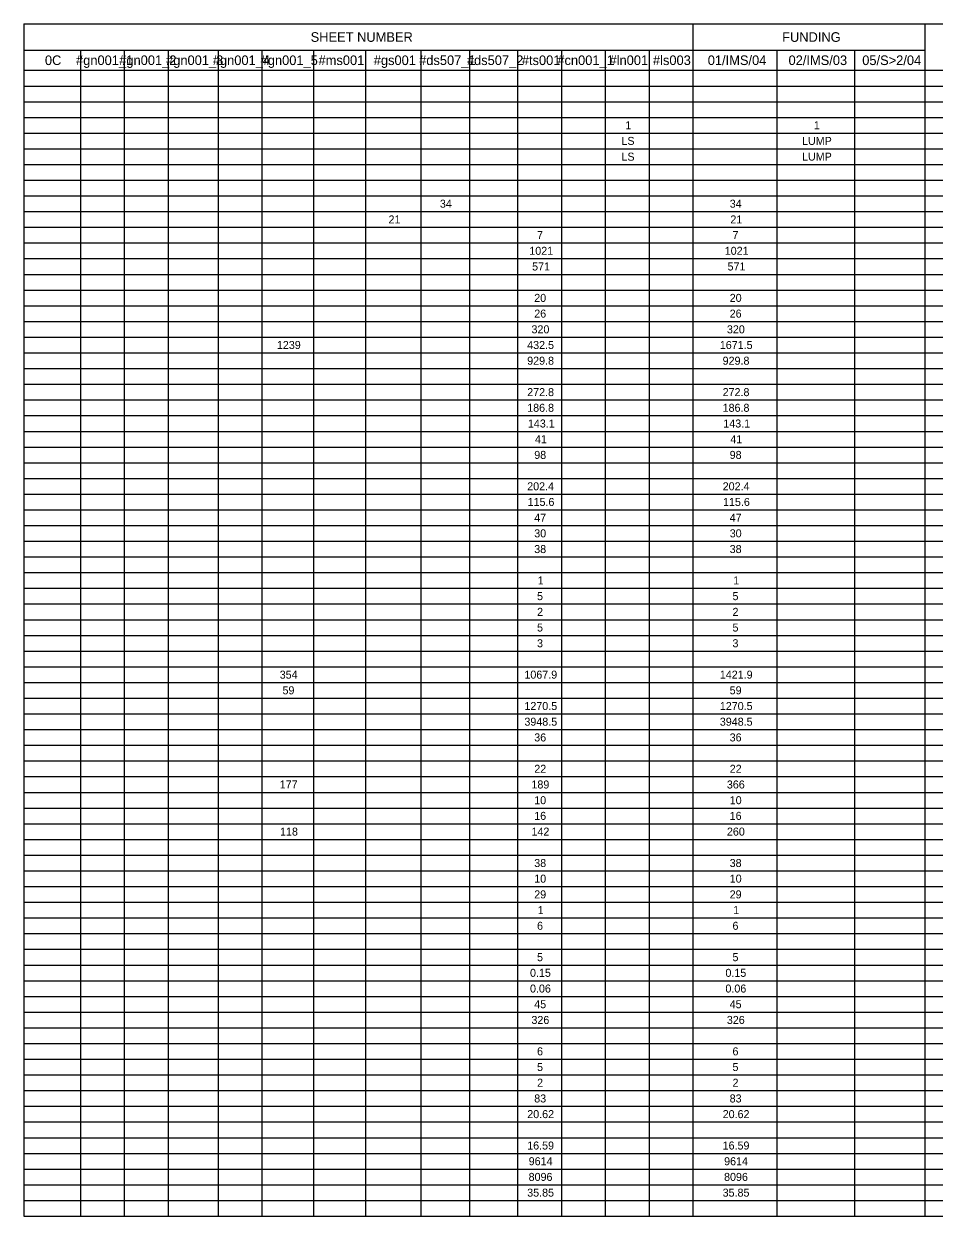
# Model space of a CAD drawing. Extents: x -542 to 295, y -281 to 32.
# Drawn here: x -541.77 to -525.86, y -100.44 to -79.59 of the extents above; entities that cross this region are included whole.
import ezdxf

# ---------------------------------------------------------------- set-up
doc = ezdxf.new("R2010")
doc.units = 0
doc.layers.add('SH_Data', color=7, linetype='Continuous')
doc.layers.add('SH_Text', color=7, linetype='Continuous')

msp = doc.modelspace()

# ---------------------------------------------------------------- linework, layer by layer
at = {"layer": 'SH_Data'}
for p, q in [((-541.766, -79.593), (-511.266, -79.593)), ((-541.766, -79.593), (-541.766, -100.444)), ((-530.071, -79.593), (-530.071, -100.444)), ((-526.016, -79.593), (-526.016, -100.444)), ((-541.766, -80.054), (-526.016, -80.054)), ((-540.776, -80.054), (-540.776, -100.444)), ((-540.01, -80.054), (-540.01, -100.444)), ((-539.244, -80.054), (-539.244, -100.444)), ((-538.371, -80.054), (-538.371, -100.444)), ((-537.605, -80.054), (-537.605, -100.444)), ((-536.701, -80.054), (-536.701, -100.444)), ((-535.796, -80.054), (-535.796, -100.444)), ((-534.828, -80.054), (-534.828, -100.444)), ((-533.976, -80.054), (-533.976, -100.444)), ((-533.135, -80.054), (-533.135, -100.444)), ((-532.369, -80.054), (-532.369, -100.444)), ((-531.603, -80.054), (-531.603, -100.444)), ((-530.837, -80.054), (-530.837, -100.444)), ((-528.602, -80.054), (-528.602, -100.444)), ((-527.25, -80.054), (-527.25, -100.444)), ((-541.766, -80.405), (-511.266, -80.405)), ((-541.766, -80.68), (-511.266, -80.68)), ((-541.766, -80.954), (-511.266, -80.954)), ((-541.766, -81.229), (-511.266, -81.229)), ((-541.766, -81.503), (-511.266, -81.503)), ((-541.766, -81.778), (-511.266, -81.778)), ((-541.766, -82.052), (-511.266, -82.052)), ((-541.766, -82.327), (-511.266, -82.327)), ((-541.766, -82.601), (-511.266, -82.601)), ((-541.766, -82.876), (-511.266, -82.876)), ((-541.766, -83.15), (-511.266, -83.15)), ((-541.766, -83.425), (-511.266, -83.425)), ((-541.766, -83.699), (-511.266, -83.699)), ((-541.766, -83.974), (-511.266, -83.974)), ((-541.766, -84.248), (-511.266, -84.248)), ((-541.766, -84.523), (-511.266, -84.523)), ((-541.766, -84.797), (-511.266, -84.797)), ((-541.766, -85.072), (-511.266, -85.072)), ((-541.766, -85.346), (-511.266, -85.346)), ((-541.766, -85.621), (-511.266, -85.621)), ((-541.766, -85.895), (-511.266, -85.895)), ((-541.766, -86.17), (-511.266, -86.17)), ((-541.766, -86.444), (-511.266, -86.444)), ((-541.766, -86.719), (-511.266, -86.719)), ((-541.766, -86.993), (-511.266, -86.993)), ((-541.766, -87.268), (-511.266, -87.268)), ((-541.766, -87.542), (-511.266, -87.542)), ((-541.766, -87.817), (-511.266, -87.817)), ((-541.766, -88.091), (-511.266, -88.091)), ((-541.766, -88.366), (-511.266, -88.366)), ((-541.766, -88.64), (-511.266, -88.64)), ((-541.766, -88.915), (-511.266, -88.915)), ((-541.766, -89.189), (-511.266, -89.189)), ((-541.766, -89.464), (-511.266, -89.464)), ((-541.766, -89.738), (-511.266, -89.738)), ((-541.766, -90.013), (-511.266, -90.013)), ((-541.766, -90.287), (-511.266, -90.287)), ((-541.766, -90.562), (-511.266, -90.562)), ((-541.766, -90.836), (-511.266, -90.836)), ((-541.766, -91.111), (-511.266, -91.111)), ((-541.766, -91.385), (-511.266, -91.385)), ((-541.766, -91.66), (-511.266, -91.66)), ((-541.766, -91.935), (-511.266, -91.935)), ((-541.766, -92.209), (-511.266, -92.209)), ((-541.766, -92.484), (-511.266, -92.484)), ((-541.766, -92.758), (-511.266, -92.758)), ((-541.766, -93.033), (-511.266, -93.033)), ((-541.766, -93.307), (-511.266, -93.307)), ((-541.766, -93.582), (-511.266, -93.582)), ((-541.766, -93.856), (-511.266, -93.856)), ((-541.766, -94.131), (-511.266, -94.131)), ((-541.766, -94.405), (-511.266, -94.405)), ((-541.766, -94.68), (-511.266, -94.68)), ((-541.766, -94.954), (-511.266, -94.954)), ((-541.766, -95.229), (-511.266, -95.229)), ((-541.766, -95.503), (-511.266, -95.503)), ((-541.766, -95.778), (-511.266, -95.778)), ((-541.766, -96.052), (-511.266, -96.052)), ((-541.766, -96.327), (-511.266, -96.327)), ((-541.766, -96.601), (-511.266, -96.601)), ((-541.766, -96.876), (-511.266, -96.876)), ((-541.766, -97.15), (-511.266, -97.15)), ((-541.766, -97.425), (-511.266, -97.425)), ((-541.766, -97.699), (-511.266, -97.699)), ((-541.766, -97.974), (-511.266, -97.974)), ((-541.766, -98.248), (-511.266, -98.248)), ((-541.766, -98.523), (-511.266, -98.523)), ((-541.766, -98.797), (-511.266, -98.797)), ((-541.766, -99.072), (-511.266, -99.072)), ((-541.766, -99.346), (-511.266, -99.346)), ((-541.766, -99.621), (-511.266, -99.621)), ((-541.766, -99.895), (-511.266, -99.895)), ((-541.766, -100.17), (-511.266, -100.17)), ((-541.766, -100.444), (-511.266, -100.444))]:
    msp.add_line(p, q, dxfattribs=at)

# ---------------------------------------------------------------- texts
at = {"layer": 'SH_Text'}
for s, height, p in [('SHEET NUMBER', 0.168, (-536.753, -79.907)), ('FUNDING', 0.168, (-528.512, -79.907)), ('0C', 0.168, (-541.398, -80.313)), ('#gn001_1', 0.168, (-540.854, -80.313)), ('#gn001_2', 0.168, (-540.099, -80.313)), ('#gn001_3', 0.168, (-539.28, -80.313)), ('#gn001_4', 0.168, (-538.463, -80.313)), ('#gn001_5', 0.168, (-537.627, -80.313)), ('#ms001', 0.168, (-536.615, -80.313)), ('#gs001', 0.168, (-535.65, -80.313)), ('#ds507_1', 0.168, (-534.857, -80.313)), ('#ds507_2', 0.168, (-534.022, -80.313)), ('#ts001', 0.168, (-533.062, -80.313)), ('#cn001_1', 0.168, (-532.441, -80.313)), ('#ln001', 0.168, (-531.529, -80.313)), ('#ls003', 0.168, (-530.77, -80.313)), ('01/IMS/04', 0.168, (-529.812, -80.313)), ('02/IMS/03', 0.168, (-528.4, -80.313)), ('05/S>2/04', 0.168, (-527.112, -80.313)), ('1', 0.14, (-531.252, -81.436)), ('1', 0.14, (-527.958, -81.436)), ('LS', 0.14, (-531.321, -81.71)), ('LUMP', 0.14, (-528.164, -81.71)), ('LS', 0.14, (-531.321, -81.985)), ('LUMP', 0.14, (-528.164, -81.985)), ('34', 0.14, (-534.494, -82.808)), ('34', 0.14, (-529.428, -82.808)), ('21', 0.14, (-535.392, -83.083)), ('21', 0.14, (-529.417, -83.083)), ('7', 0.14, (-532.796, -83.357)), ('7', 0.14, (-529.38, -83.357)), ('1021', 0.14, (-532.931, -83.632)), ('1021', 0.14, (-529.515, -83.632)), ('571', 0.14, (-532.882, -83.906)), ('571', 0.14, (-529.466, -83.906)), ('20', 0.14, (-532.845, -84.455)), ('20', 0.14, (-529.428, -84.455)), ('26', 0.14, (-532.845, -84.73)), ('26', 0.14, (-529.429, -84.73)), ('320', 0.14, (-532.893, -85.005)), ('320', 0.14, (-529.477, -85.005)), ('1239', 0.14, (-537.343, -85.279)), ('432.5', 0.14, (-532.968, -85.279)), ('1671.5', 0.14, (-529.601, -85.279)), ('929.8', 0.14, (-532.968, -85.554)), ('929.8', 0.14, (-529.552, -85.554)), ('272.8', 0.14, (-532.968, -86.103)), ('272.8', 0.14, (-529.552, -86.103)), ('186.8', 0.14, (-532.968, -86.377)), ('186.8', 0.14, (-529.552, -86.377)), ('143.1', 0.14, (-532.956, -86.652)), ('143.1', 0.14, (-529.54, -86.652)), ('41', 0.14, (-532.833, -86.926)), ('41', 0.14, (-529.417, -86.926)), ('98', 0.14, (-532.845, -87.201)), ('98', 0.14, (-529.429, -87.201)), ('202.4', 0.14, (-532.968, -87.75)), ('202.4', 0.14, (-529.551, -87.75)), ('115.6', 0.14, (-532.961, -88.024)), ('115.6', 0.14, (-529.545, -88.024)), ('47', 0.14, (-532.845, -88.299)), ('47', 0.14, (-529.429, -88.299)), ('30', 0.14, (-532.845, -88.573)), ('30', 0.14, (-529.428, -88.573)), ('38', 0.14, (-532.845, -88.848)), ('38', 0.14, (-529.429, -88.848)), ('1', 0.14, (-532.784, -89.397)), ('1', 0.14, (-529.368, -89.397)), ('5', 0.14, (-532.796, -89.671)), ('5', 0.14, (-529.38, -89.671)), ('2', 0.14, (-532.795, -89.946)), ('2', 0.14, (-529.379, -89.946)), ('5', 0.14, (-532.796, -90.22)), ('5', 0.14, (-529.38, -90.22)), ('3', 0.14, (-532.796, -90.495)), ('3', 0.14, (-529.38, -90.495)), ('354', 0.14, (-537.294, -91.044)), ('1067.9', 0.14, (-533.017, -91.044)), ('1421.9', 0.14, (-529.601, -91.044)), ('59', 0.14, (-537.245, -91.318)), ('59', 0.14, (-529.429, -91.318)), ('1270.5', 0.14, (-533.017, -91.593)), ('1270.5', 0.14, (-529.601, -91.593)), ('3948.5', 0.14, (-533.017, -91.867)), ('3948.5', 0.14, (-529.601, -91.867)), ('36', 0.14, (-532.845, -92.142)), ('36', 0.14, (-529.429, -92.142)), ('22', 0.14, (-532.844, -92.691)), ('22', 0.14, (-529.428, -92.691)), ('177', 0.14, (-537.294, -92.965)), ('189', 0.14, (-532.894, -92.965)), ('366', 0.14, (-529.478, -92.965)), ('10', 0.14, (-532.845, -93.24)), ('10', 0.14, (-529.428, -93.24)), ('16', 0.14, (-532.845, -93.514)), ('16', 0.14, (-529.429, -93.514)), ('118', 0.14, (-537.288, -93.789)), ('142', 0.14, (-532.893, -93.789)), ('260', 0.14, (-529.477, -93.789)), ('38', 0.14, (-532.845, -94.338)), ('38', 0.14, (-529.429, -94.338)), ('10', 0.14, (-532.845, -94.612)), ('10', 0.14, (-529.428, -94.612)), ('29', 0.14, (-532.845, -94.887)), ('29', 0.14, (-529.429, -94.887)), ('1', 0.14, (-532.784, -95.161)), ('1', 0.14, (-529.368, -95.161)), ('6', 0.14, (-532.796, -95.436)), ('6', 0.14, (-529.38, -95.436)), ('5', 0.14, (-532.796, -95.985)), ('5', 0.14, (-529.38, -95.985)), ('0.15', 0.14, (-532.919, -96.259)), ('0.15', 0.14, (-529.503, -96.259)), ('0.06', 0.14, (-532.919, -96.534)), ('0.06', 0.14, (-529.503, -96.534)), ('45', 0.14, (-532.845, -96.808)), ('45', 0.14, (-529.429, -96.808)), ('326', 0.14, (-532.894, -97.083)), ('326', 0.14, (-529.478, -97.083)), ('6', 0.14, (-532.796, -97.632)), ('6', 0.14, (-529.38, -97.632)), ('5', 0.14, (-532.796, -97.906)), ('5', 0.14, (-529.38, -97.906)), ('2', 0.14, (-532.795, -98.181)), ('2', 0.14, (-529.379, -98.181)), ('83', 0.14, (-532.845, -98.456)), ('83', 0.14, (-529.429, -98.456)), ('20.62', 0.14, (-532.967, -98.73)), ('20.62', 0.14, (-529.551, -98.73)), ('16.59', 0.14, (-532.968, -99.279)), ('16.59', 0.14, (-529.552, -99.279)), ('9614', 0.14, (-532.942, -99.554)), ('9614', 0.14, (-529.526, -99.554)), ('8096', 0.14, (-532.943, -99.828)), ('8096', 0.14, (-529.527, -99.828)), ('35.85', 0.14, (-532.968, -100.103)), ('35.85', 0.14, (-529.552, -100.103))]:
    msp.add_text(s, height=height, dxfattribs=at).set_placement(p)

doc.saveas('drawing.dxf')
